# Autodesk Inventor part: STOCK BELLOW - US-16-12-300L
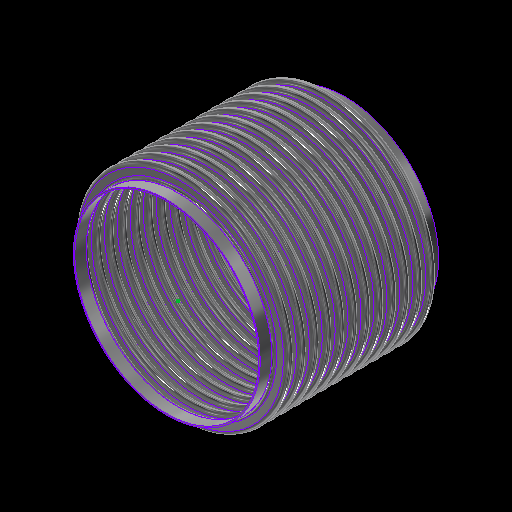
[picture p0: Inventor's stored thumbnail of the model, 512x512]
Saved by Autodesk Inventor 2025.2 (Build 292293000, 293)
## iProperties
Category: 16 GA (0.060 THICK)
RuleStatus: InUse
Created: 2024-01
Part Number: STOCK BELLOW - US-16-12-300L
Project: =STOCK BELLOWS: <Stock Number><SFILL>
Material: ASTM A240-304
Description: =STOCK BELLOWS: <Stock Number>, <SID_> I.D., <SOD_> O.D., <SPLY_> PLY, <Category>, <SNET_CONS> CONS.<PITCH_><STANGENT_> TANGENT<SFILL>
Document SubType Name: Sheet Metal
Designer: GS
Stock Number: U.S-16-12-300L
Surface Area: 25894.3 cm^2
Volume: 3910.44 cm^3
Sheet Metal Rule: Default
Appearance: STAINLESS STEEL
Mass: 31507.5 g
Density: 8.05729 g/cm^3
THK: 0.036
ID: 3.500
OD: 4.250
CONS_: 2
PITCH: 0.500
TANGENT: 0.500
BELLOWS_UPSET: 0.000
d79: 1.000
d82: 1.000
d83: 26.000
d84: 24.000
d174: 8
d214: 8
STHK_: 0.060
SID_: 16.000
SOD_: 18.500
SPITCH_: 1.125
STANGENT__: 1.000
SBELLOWS_UPSET_: 0.000
SDIFF_TAN: 1.000
d252: 2
d275: 2
d287: 0.050
d289: 0.500
d290: 0.000
SOD_NECK: 16 1/4
PLY: 1
PSET: 4.178
PBAR: 1.035
COUNTER: 1.500
NET_TUBE: 3.071
CONS: 2
S_CONS: 0
NET_CONS: 2
ID_M: 88.90 mm
OD_M: 107.95 mm
THK_M: 0.91 mm
ID_U: 3.500 in
OD_U: 4.250 in
THK_U: 0.036 in
TANGENT2: 0.500
TAN_TO_TAN: 1.000 in
d80: 2.571
d81: 10
SID: 2.375
SCONS_: 12
SPITCH: 0.250
STANGENT_: 1.000
SBELLOWS_UPSET: 0.000
SNET_CONS: 12
SS_CONS: 0
SCONS: 8
d190: 8
d191: 1
d192: 1
d193: 8
d194: 0
SIZE: 16.00
PRESSURE: 300
d230: 8
STANGENT: 4.000
SPLY_: 2
d233: 8
d234: 0
d263: 2
d265: 1
d268: 2
d269: 0
d286: 2
d288: 1
d291: 2
d292: 0
SREROLL: 0.750
BLETP: 1.000 ul
PRES_Copy: 85
MATTABLE: 20 GA (0.036 THICK)
PART_NUMBER: U.S-16-12-300L
PITCH_: =, <SPITCH_> PITCH,
CFILL: .
SFILL: .
MESH: ,
COMP: 2.3
EXT: 1.15
LAT: 0.60
ANG: 573
ASR: 6268
LSR: 15352
ANSR: 4069
PRES: 300
COMPM: 23.0
EXTM: 11.5
LATM: 6.00
ASRM: 1097.715
PRESM: 20.684
LSRM: 2688.596
ANSRM: 712.604
TEMPMIN: 20
TEMPMAX: 800
TEMPMINM: -7
TEMPMAXM: 427
WEIGHTM: 31.508
WEIGHT: 69.462
Author: GS
Keywords: 20 GA (0.036 THICK)
Comments: =STOCK BELLOW - <STOCK NUMBER>
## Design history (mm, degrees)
sketch "Sketch2"
  geometry: L1 (0, -177.245)-(0, 562.856) reference; L2 (45.364, 0)-(44.45, 0); L3 (48.082, -2.718)-(50.343, -2.718); L4 (48.082, -3.632)-(50.343, -3.632); L5 (50.343, -9.982)-(48.082, -9.982); L6 (50.343, -9.068)-(48.082, -9.068); L7 (45.364, -12.7)-(44.45, -12.7); L8 (48.082, 0)-(48.082, -12.7); L9 (50.343, -6.35)-(53.975, -6.35); L10 (44.45, 0)-(44.45, -12.7); L11 (20.376, 102.841)-(20.376, 101.926); L12 (58.262, 457.127)-(58.262, 349.177); L13 (58.262, 444.427)-(58.262, 336.477); L14 (93.133, -58.817)-(93.133, -71.517); L15 (118.746, -66.401)-(118.746, -66.401); L16 (50.343, -9.068)-(50.343, -9.982); L17 (48.082, -9.068)-(48.082, -9.982); L18 (48.082, -9.525)-(50.343, -9.525); L19 (53.975, 0)-(53.975, -12.7); L20 (-50.343, -9.068)-(-50.343, -9.982); L21 (-50.343, -2.718)-(-48.082, -2.718); L22 (-50.343, -3.632)-(-48.082, -3.632); L23 (-48.082, -9.068)-(-50.343, -9.068); L24 (-50.343, -9.525)-(-48.082, -9.525); L25 (-48.082, -9.982)-(-50.343, -9.982); L26 (-48.082, -9.068)-(-48.082, -9.982); L27 (-44.45, 0.653)-(-44.45, -12.047); L28 (-48.082, -6.35)-(-44.45, -6.35); L29 (-50.343, 0.653)-(-50.343, -12.7); L30 (-53.061, 0)-(-53.975, 0); L31 (-53.975, 0)-(-53.975, -12.7); L32 (-53.061, -12.7)-(-53.975, -12.7); A1 r 2.718 centre (48.082, 0) between (45.364, 0) and (48.082, -2.718); A2 r 3.632 centre (48.082, 0) between (44.45, 0) and (48.082, -3.632); A3 r 3.632 centre (50.343, -6.35) between (50.343, -9.982) and (50.343, -2.718); A4 r 2.718 centre (50.343, -6.35) between (50.343, -9.068) and (50.343, -3.632); A5 r 2.718 centre (48.082, -12.7) between (48.082, -9.982) and (45.364, -12.7); A6 r 3.632 centre (48.082, -12.7) between (48.082, -9.068) and (44.45, -12.7); A7 r 3.175 centre (50.343, -6.35) between (50.343, -9.525) and (53.518, -6.35); A8 r 3.175 centre (48.082, -12.7) between (48.082, -9.525) and (44.907, -12.7); A9 r 2.718 centre (-50.343, -12.7) between (-50.343, -9.982) and (-53.061, -12.7); A10 r 2.718 centre (-48.082, -6.35) between (-48.082, -9.068) and (-48.082, -3.632); A11 r 3.175 centre (-48.082, -6.35) between (-48.082, -9.525) and (-44.907, -6.35); A12 r 3.632 centre (-48.082, -6.35) between (-48.082, -9.982) and (-48.082, -2.718); A13 r 3.175 centre (-50.343, -12.7) between (-50.343, -9.525) and (-53.518, -12.7); A14 r 3.632 centre (-50.343, -12.7) between (-50.343, -9.068) and (-53.975, -12.7); A15 r 2.718 centre (-50.343, 0) between (-53.061, 0) and (-50.343, -2.718); A16 r 3.632 centre (-50.343, 0) between (-53.975, 0) and (-50.343, -3.632); 10 further points
  constraints: 62 end point, 38 point on circle, 20 tangent, 16 centre point, 12 parallel, 9 midpoint, 7 vertical, 6 coincident, 6 concentric, 6 point on line, 4 equal radius, 4 perpendicular, 3 horizontal, 1 collinear, 1 horizontal alignment, 10 other
  dimensions: "THK" = 0.9144 distance of L11.start L11.end; "ID" = 88.9 distance of L11.end point (20.376, 13.026); "OD" = 107.95 distance of L12.start L12.end; "PITCH" = 12.7 distance of L12.start L13.start; "TANGENT" = 12.7 distance of L14.start L14.end; "BELLOWS_UPSET" = 0 distance of L15.start L15.end; "d43" = 88.9 diameter of L10 L1 (= ID); "d44" = 107.95 diameter of L9.end L1 (= OD); "d45" = 0.9144 distance between parallel lines of L5 L6 (computed from THK, PLY); "d46" = 3.6322 radius of A3 (computed from PITCH, THK, PLY); "UPSET_PITCH" = 12.7 distance of L2.end L7.end (derived); "SIDEWALL_ANGLE" = 360 deg dimension on L3 L9 (derived); "CON_GAP" = 5.4356 distance of point (48.082, -9.068) point (48.082, -3.632) (derived); "TAN1" = 4.98728 dimension on A8 (derived); "TAN2" = 4.98728 dimension on A7 (derived); "LEG1" = 2.2606 distance of L18.start L18.end (derived); "d278" = 0.9144 distance between parallel lines of L25 L23 (derived); "d279" = 3.6322 radius of A12 (derived); "d280" = 12.7 distance of L30.end L31.end (derived); "d281" = 360 deg dimension on L21 L28 (derived); "d282" = 5.4356 distance of point (-50.343, -9.068) point (-50.343, -3.632) (derived); "d283" = 4.98728 dimension on A13 (derived); "d284" = 4.98728 dimension on A11 (derived); "d285" = 2.2606 distance of L24.start L24.end (derived); "d293" = 88.9 diameter of L27 L1 (derived); "d294" = 107.95 diameter of L31 L1 (derived)
  node "Sketch Rectangular Pattern1" dims "d31" = 25.4, "ID" = 88.9
  node "Sketch Rectangular Pattern2" dims "d39" = 25.4, "PITCH" = 12.7
revolve "CONS" stored, may be unused: angle "d48" = 90 deg
node "BELLOW MIDPLANE"
pattern_linear "Rectangular Pattern2" dims "d52" = 12.7 (= UPSET_PITCH)
sketch "Sketch5"
  geometry: C1 r 45.364 at (0, 0) reference; C2 r 44.45 at (0, 0) reference
extrude "TANGENT" new body sketch "Sketch5" distance "d53" = 12.7 (= TANGENT); taper "d54" = 0 deg
revolve "SAMETAN" stored, may be unused: angle "d65" = 90 deg
revolve "DIFFTAN" stored, may be unused: angle "d70" = 90 deg
sketch "Sketch9"
  geometry: L1 (53.319, 0)-(-53.319, 0) reference; L2 (0, -17.78)-(0, 17.78) reference; L3 (38.085, 0)-(-38.085, 0); L4 (38.085, -11.906)-(38.085, 11.906); L5 (25.385, -11.906)-(25.385, 11.906); L6 (13.15, 11.906)-(13.15, -11.906); L7 (-25.385, -11.906)-(-25.385, 11.906); L8 (-38.085, -11.906)-(-38.085, 11.906); L9 (37.291, -11.906)-(37.291, 11.906); L10 (38.085, -11.906)-(37.291, -11.906); L11 (38.085, 11.906)-(37.291, 11.906); L12 (13.546, 11.906)-(12.753, 11.906); L13 (12.753, 11.906)-(12.753, -11.906); L14 (12.753, -11.906)-(13.546, -11.906); L15 (13.546, -11.906)-(13.546, 11.906); L16 (-13.546, 11.906)-(-13.546, -11.906); L17 (-13.15, 11.906)-(-13.15, -11.906); L18 (-13.546, -11.906)-(-12.753, -11.906); L19 (-12.753, -11.906)-(-12.753, 11.906); L20 (-12.753, 11.906)-(-13.546, 11.906); L21 (-38.085, -11.906)-(-37.291, -11.906); L22 (-37.291, -11.906)-(-37.291, 11.906); L23 (-37.291, 11.906)-(-38.085, 11.906); L24 (-38.085, 11.906)-(-38.085, -11.906); L25 (38.085, -0.397)-(-38.085, -0.397); L26 (-38.085, -0.397)-(-38.085, 0.397); L27 (-38.085, 0.397)-(38.085, 0.397); L28 (38.085, 0.397)-(38.085, -0.397); L29 (-38.085, 11.906)-(38.085, 11.906); L30 (38.085, 11.906)-(38.085, 12.7); L31 (38.085, 12.7)-(-38.085, 12.7); L32 (-38.085, 12.7)-(-38.085, 11.906); L33 (38.085, -11.906)-(-38.085, -11.906); L34 (-38.085, -11.906)-(-38.085, -12.7); L35 (-38.085, -12.7)-(38.085, -12.7); L36 (38.085, -12.7)-(38.085, -11.906); 30 further points
  constraints: 68 end point, 13 midpoint, 13 parallel, 8 horizontal, 7 perpendicular, 6 equal length, 3 point on line, 2 vertical, 14 other
  dimensions: "d115" = 23.8125 distance of L4.start L4.end (derived); "d116" = 12.7 distance between parallel lines of L4 L5 (derived); "d117" = 12.23516 distance between parallel lines of L5 L6 (derived); "d125" = 38.53427 distance between parallel lines of L7 L6 (derived); "d127" = 12.7 distance between parallel lines of L8 L7 (derived); "d128" = 24.93516 distance between parallel lines of L6 L4 (derived); "d130" = 76.16943 distance between parallel lines of L8 L4 (derived); "RULER_THK" = 0.79375 distance between parallel lines of L4 L9; "d135" = 0.79375 distance of L13.end L14.end (derived); "d138" = 26.29911 distance of L13.end L16.end (derived); "d143" = 0.79375 distance of L22.end L8.end (derived); "d144" = 0.79375 distance between parallel lines of L27 L25 (derived)
extrude "RULER" join sketch "Sketch9" distance "d149" = 0.79375 (derived); taper "d150" = 0 deg
extrude "BARS" join sketch "Sketch9" distance "d151" = 0.79375 (derived); taper "d152" = 0 deg
pattern_linear "Rectangular Pattern4" dims "d155" = 26.29911 (derived)
sketch "Sketch13"
  geometry: L1 (93.149, -52.467)-(93.149, -77.867); L2 (206.248, 0)-(203.2, 0); L3 (206.248, -28.575)-(203.2, -28.575); L4 (226.282, -22.955)-(211.868, -22.955); L5 (226.282, -19.907)-(211.868, -19.907); L6 (226.282, -14.287)-(234.95, -14.287); L7 (211.868, -5.62)-(226.282, -5.62); L8 (211.868, 0)-(211.868, -28.575); L9 (203.2, 0)-(203.2, -28.575); L10 (58.254, -26.531)-(58.254, -496.431); L11 (58.254, -55.106)-(58.254, -525.006); L12 (58.254, -112.256)-(58.254, -582.156); L13 (58.254, -140.831)-(58.254, -610.731); L14 (58.254, -169.406)-(58.254, -639.306); L15 (58.254, -197.981)-(58.254, -667.881); L16 (58.254, -226.556)-(58.254, -696.456); L17 (58.254, -83.681)-(58.254, -553.581); L18 (20.376, 103.45)-(20.376, 101.926); L19 (211.868, -8.668)-(226.282, -8.668); L20 (0, -856.437)-(0, 263.431) reference; L21 (-46.99, 0)-(281.94, 0) reference; A1 r 5.62 centre (211.868, 0) between (206.248, 0) and (211.868, -5.62); A2 r 5.62 centre (211.868, -28.575) between (211.868, -22.955) and (206.248, -28.575); A3 r 8.668 centre (211.868, -28.575) between (211.868, -19.907) and (203.2, -28.575); A4 r 5.62 centre (226.282, -14.287) between (226.282, -19.907) and (226.282, -8.668); A5 r 8.668 centre (226.282, -14.287) between (226.282, -22.955) and (226.282, -5.62); A6 r 8.668 centre (211.868, 0) between (203.2, 0) and (211.868, -8.668); 6 further points; 1 other entity
  constraints: 38 end point, 15 point on circle, 9 tangent, 6 centre point, 6 parallel, 5 vertical alignment, 4 point on line, 4 vertical, 3 coincident, 3 concentric, 2 collinear, 2 equal radius, 1 horizontal, 1 perpendicular, 23 other
  dimensions: "SBELLOWS_UPSET_" = 0 distance of point (118.762, -66.401) point (118.762, -66.401); "STOTAL_THK_BELLOW__" = 3.048 distance between parallel lines of L4 L5 (derived); "d224" = 8.66775 radius of A5 (derived); "d225" = 28.575 distance of L2.end L3.end (derived); "SSIDEWALL_ANGLE_" = 360 deg dimension on L7 L6 (derived); "SSCON_GAP_" = 11.2395 distance of point (211.868, -19.907) point (211.868, -8.668) (derived); "d235" = 406.4 diameter of L9 L20 (derived); "d236" = 469.9 diameter of L6.end L20 (derived)
  node "Sketch Rectangular Pattern4" dims "d228" = 25.4
  node "Sketch Rectangular Pattern5" dims "d229" = 25.4
revolve "SBELLOW" stored, may be unused: angle "d197" = 90 deg
pattern_linear "Rectangular Pattern5" dims "d204" = 28.575 (derived)
revolve "STANGENT" stored, may be unused: angle "d240" = 90 deg
revolve "SSAMETAN" stored, may be unused: angle "d241" = 90 deg
revolve "SDIFFTAN" stored, may be unused: angle "d246" = 90 deg
revolve "INVCON" stored, may be unused: angle "d295" = 90 deg
pattern_linear "Rectangular Pattern6" dims "d298" = 12.7 (derived)
revolve "INVTANGENT" stored, may be unused: angle "d302" = 90 deg
revolve "INVSAMETAN" stored, may be unused: angle "d307" = 90 deg
revolve "INVDIFFTAN" stored, may be unused: angle "d312" = 90 deg
sketch "ID BELLOW MOUNT CALC"
  geometry: L1 (44.45, 0)-(38.1, 0); L2 (38.1, 0)-(38.1, 12.7); L3 (38.1, 12.7)-(44.45, 12.7); L4 (44.45, 12.7)-(44.45, 0); L5 (36.513, 12.7)-(35.598, 12.7); L6 (35.598, 12.7)-(35.598, 0); L7 (35.598, 0)-(36.513, 0); L8 (36.513, 0)-(36.513, 12.7); L9 (0, -2.54)-(0, 15.24) reference; L10 (-8.89, 0)-(53.34, 0) reference; 1 further point
  constraints: 16 end point, 5 parallel, 2 collinear, 2 horizontal, 2 perpendicular
  dimensions: "d314" = 12.7 distance of L5.end L6.end (derived); "d315" = 0.9144 distance of L5.start L5.end (derived); "IG" = 1.5875 distance between parallel lines of L2 L8; "PIPE_OD" = 88.9 diameter of L4 L9; "PIPE_WALL" = 6.35 distance of L2.end L3.end; "ID_MT_BELLOW" = 71.1962 diameter of L6 L9 (derived)
revolve "CFILL" stored, may be unused: angle "d320" = 90 deg
pattern_linear "Rectangular Pattern7" dims "d323" = 12.7 (derived)
revolve "SFILL" stored, may be unused: angle "d324" = 90 deg
pattern_linear "Rectangular Pattern8" dims "d327" = 28.575 (derived)
node "STOCK BELLOW MIDPLANE"
node "BELLOW"
sketch "Sketch6"
  geometry: L1 (-12.7, 45.364)-(0, 45.364); L2 (0, 45.364)-(0, 44.45); L3 (0, 44.45)-(-12.7, 44.45); L4 (-12.7, 44.45)-(-12.7, 45.364); L5 (10.16, 0)-(-60.96, 0) reference; L6 (-38.1, -89.422)-(-38.1, 153.44) reference; 1 further point
  constraints: 8 end point, 2 parallel, 1 horizontal, 1 perpendicular
  dimensions: "d61" = 12.7 distance of L2.end L3.end (derived); "d62" = 0.9144 distance of L1.end L2.end (derived); "d63" = 88.9 diameter of L3 L5 (derived); "d64" = 25.4 distance between parallel lines of L4 L6 (derived)
sketch "Sketch12"
  geometry: 1 further point
sketch "Sketch14"
  geometry: L1 (-25.4, 206.248)-(0, 206.248); L2 (0, 206.248)-(0, 203.2); L3 (0, 203.2)-(-25.4, 203.2); L4 (-25.4, 203.2)-(-25.4, 206.248); L5 (5.08, 0)-(-30.48, 0) reference; L6 (0, -41.25)-(0, 247.498) reference; 1 further point
  constraints: 8 end point, 2 parallel, 1 collinear, 1 horizontal, 1 perpendicular
  dimensions: "d237" = 3.048 distance of L3.end L1.start (derived); "d238" = 406.4 diameter of L3 L5 (derived); "d239" = 25.4 distance of L1.start L1.end (derived); "SOD_NECK" = 412.496 diameter of L1 L5 (derived)
sketch "Sketch15"
  geometry: L1 (-41.25, 0)-(247.498, 0) reference; L2 (203.2, -342.9)-(206.248, -342.9); L3 (206.248, -342.9)-(206.248, -368.3); L4 (206.248, -368.3)-(203.2, -368.3); L5 (203.2, -368.3)-(203.2, -342.9); L6 (0, -444.5)-(0, 88.9) reference; 1 further point
  constraints: 8 end point, 2 parallel, 1 horizontal, 1 perpendicular
  dimensions: "d205" = 25.4 distance of L4.end L2.start (derived); "d206" = 3.048 distance of L3.end L4.end (derived); "d207" = 406.4 diameter of L5 L6 (derived); "d208" = 342.9 distance between parallel lines of L1 L2 (derived)
node "TANGENT_"
node "SAME_TAN"
sketch "Sketch8"
  geometry: L1 (45.364, -25.4)-(44.45, -25.4); L2 (44.45, -25.4)-(44.45, -38.1); L3 (44.45, -38.1)-(45.364, -38.1); L4 (45.364, -38.1)-(45.364, -25.4); L5 (0, -48.26)-(0, 22.86) reference; L6 (-89.422, 0)-(153.44, 0) reference; 1 further point
  constraints: 8 end point, 2 parallel, 1 horizontal, 1 perpendicular
  dimensions: "d66" = 88.9 diameter of L2 L5 (derived); "TOTAL_THK_BELLOW" = 0.9144 distance of L2.end L3.end (derived); "d68" = 25.4 distance between parallel lines of L1 L6 (derived); "d69" = 12.7 distance of L1.end L2.end (derived)
node "DIFF_TAN"
node "Sketch Rectangular Pattern3" dims "d138" = 26.29911 (derived), "d141" = 25.4
node "SBELLOW_"
node "STANGENT_"
node "SSAME_TAN"
sketch "Sketch16"
  geometry: L1 (206.248, -342.9)-(203.2, -342.9); L2 (203.2, -342.9)-(203.2, -368.3); L3 (203.2, -368.3)-(206.248, -368.3); L4 (206.248, -368.3)-(206.248, -342.9); L5 (0, -444.5)-(0, 88.9) reference; L6 (-41.25, 0)-(247.498, 0) reference; 1 further point
  constraints: 8 end point, 2 parallel, 1 horizontal, 1 perpendicular
  dimensions: "SDIFF_TAN" = 25.4 distance of L3.end L1.start; "d243" = 3.048 distance of L2.end L3.end (derived); "d244" = 342.9 distance between parallel lines of L1 L6 (derived); "d245" = 406.4 diameter of L2 L5 (derived)
node "SDIFF_TAN"
body "Solid15"
sketch "Sketch17"
  geometry: L1 (53.975, 12.7)-(53.061, 12.7); L2 (53.061, 12.7)-(53.061, 0); L3 (53.061, 0)-(53.975, 0); L4 (53.975, 0)-(53.975, 12.7); L5 (0, -2.54)-(0, 15.24) reference; L6 (-10.795, 0)-(64.77, 0) reference; 2 further points
  constraints: 8 end point, 2 parallel, 1 horizontal, 1 midpoint, 1 perpendicular, 1 point on line
  dimensions: "INVTANGENT" = 12.7 distance of L3.end L1.start (derived); "d300" = 0.9144 distance of L1.start L1.end (derived); "d301" = 107.95 diameter of L4 L5 (derived)
body "Solid16"
sketch "Sketch18"
  geometry: L1 (53.975, -25.4)-(53.061, -25.4); L2 (53.061, -25.4)-(53.061, -38.1); L3 (53.061, -38.1)-(53.975, -38.1); L4 (53.975, -38.1)-(53.975, -25.4); L5 (-10.795, 0)-(64.77, 0) reference; L6 (0, -48.26)-(0, 22.86) reference; 1 further point
  constraints: 8 end point, 2 parallel, 1 horizontal, 1 perpendicular
  dimensions: "d303" = 25.4 distance between parallel lines of L1 L5 (derived); "d304" = 12.7 distance of L3.end L1.start (derived); "d305" = 0.9144 distance of L2.end L3.end (derived); "d306" = 107.95 diameter of L4 L6 (derived)
body "Solid17"
sketch "Sketch19"
  geometry: L1 (53.975, -25.4)-(53.061, -25.4); L2 (53.061, -25.4)-(53.061, -38.1); L3 (53.061, -38.1)-(53.975, -38.1); L4 (53.975, -38.1)-(53.975, -25.4); L5 (0, -48.26)-(0, 22.86) reference; L6 (-10.795, 0)-(64.77, 0) reference; 1 further point
  constraints: 8 end point, 2 parallel, 1 horizontal, 1 perpendicular
  dimensions: "d308" = 12.7 distance of L1.end L2.end (derived); "d309" = 107.95 diameter of L4 L5 (derived); "d310" = 0.9144 distance of L2.end L3.end (derived); "d311" = 25.4 distance between parallel lines of L1 L6 (derived)
body "Solid18"
body "Solid19"
body "Solid20"
other parameters: "BMPL" = -171.45, "PSET" = 106.1212 (computed from OD, THK, PLY) [user parameter], "PBAR" = 26.29911 (= 0.570796 x PITCH + OD - ID) [user parameter; used in 1 equation term], "COUNTER" = 15 [user parameter], "NET_TUBE" = 77.99823 (computed from CONS_, PBAR, TANGENT) [user parameter], "S_CONS" = 0 [user parameter; used in 1 equation term], "ID_M" = 88.9 (= ID) [user parameter], "OD_M" = 107.95 (= OD) [user parameter], "THK_M" = 0.9144 (= THK) [user parameter], "ID_U" = 88.9 (= ID) [user parameter], "OD_U" = 107.95 (= OD) [user parameter], "THK_U" = 0.9144 (= THK) [user parameter], "D_UNITS" = 0 [user parameter], "TANGENT2" = 12.7 [user parameter], "TAN_TO_TAN" = 25.4 [user parameter], "OD_NECK" = 90.7288 [user parameter], "d79" = 25.4, "d80" = 65.29823 [user parameter], "d82" = 25.4, "d83" = 660.4, "d84" = 609.6, "sa_0" = 4, "FRAME_THK" = 0.79375 [user parameter], "CON_FLAT" = 12.23516 [user parameter], "SID" = 60.325 [user parameter], "SPITCH" = 6.35 [user parameter], "STANGENT_" = 25.4 [user parameter], "SBELLOWS_UPSET" = 0 [user parameter], "SS_CONS" = 0 [user parameter], "STAN_TO_TAN_" = 342.9 [user parameter], "d100" = 3.048 [user parameter], "d191" = 25.4 [user parameter], "d194" = 0 [user parameter], "STANGENT" = 101.6 [user parameter], "d234" = 0 [user parameter], "SUPSET_PITCH_" = 28.575 [user parameter], "d269" = 0 [user parameter], "d287" = 1.27, "d289" = 12.7, "d290" = 0, "d292" = 0 [user parameter], "Thickness" = 3.048 (derived), "KFactor" = 4.4, "BendRadius" = 3.048 (derived), "BendReliefWidth" = 3.048 (derived), "BendReliefDepth" = 1.524 (derived), "CornerReliefSize" = 12.192 (derived), "SeamGap" = 0.00508, "MinimumRemnant" = 6.096 (derived), "TransitionRadius" = 3.048 (derived), "JacobiRadiusSize" = 3.048 (derived), "GapSize" = 3.048 (derived), "SREROLL" = 19.05 [user parameter], "CUR_STK_PITCH" = 28.575 [user parameter], "d328" = -171.45 (derived), "ASR" = 62680 [user parameter], "LSR" = 153520 [user parameter], "ANSR" = 40690 [user parameter], "BLETP" = 1 [user parameter], "ASRM" = 10977.1484 [user parameter], "PRESM" = 206.83949 [user parameter], "LSRM" = 26885.9576 [user parameter], "ANSRM" = 7126.0397 [user parameter], "TEMPMIN" = 2664.83333 [user parameter], "TEMPMAX" = 6998.16667 [user parameter], "TEMPMINM" = 2664.83333 [user parameter], "TEMPMAXM" = 6998.16667 [user parameter], "WEIGHT" = 315.07502 [user parameter], "WEIGHTM" = 0.31508 [user parameter]
